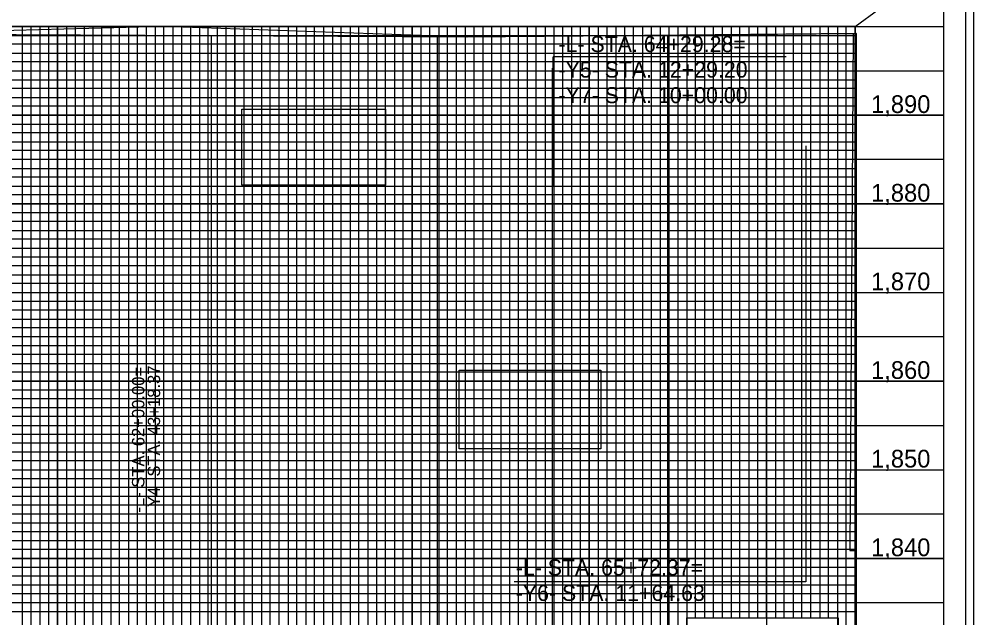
# Model space of a CAD drawing. Extents: x 557032 to 562069, y 513430 to 515874.
# Drawn here: x 558178 to 558716, y 514991 to 515328 of the extents above; entities that cross this region are included whole.
import ezdxf

# ---------------------------------------------------------------- set-up
doc = ezdxf.new("R2010")
doc.units = 0
for name, color, linetype in [('Exist Vertical Profile Vertical Axis Label', 7, 'Continuous'), ('Prop DSN Text', 7, 'Continuous'), ('Prop Vertical Profile Curve Label', 7, 'Continuous'), ('Prop VPI Label', 7, 'Continuous'), ('Scratch_Level_1', 7, 'Continuous'), ('Scratch_Level_5', 7, 'Continuous'), ('Sheet DOT Grid CELL', 7, 'Continuous'), ('Sheet Layout Profile Border Port 2', 7, 'Continuous'), ('Sheet Plot Border Inside CELL', 7, 'Continuous'), ('Sheet Plot Border Outside CELL', 7, 'Continuous'), ('Sheet Profile CELL', 7, 'Continuous'), ('Sheet Profile Grid Major CELL', 7, 'Continuous'), ('Sheet Profile Grid Middle CELL', 7, 'Continuous'), ('Sheet Profile Grid Minor CELL', 7, 'Continuous')]:
    doc.layers.add(name, color=color, linetype=linetype)

msp = doc.modelspace()

# ---------------------------------------------------------------- linework, layer by layer
at = {"layer": 'Prop DSN Text'}
for p, q in [((558554.45, 514990.68), (558639.79, 514990.68)), ((558554.45, 514914.28), (558554.45, 514990.68)), ((558639.79, 514990.68), (558639.79, 514914.28))]:
    msp.add_line(p, q, dxfattribs=at)
at = {"layer": 'Prop Vertical Profile Curve Label'}
for points in [[(558303.41, 515277.61), (558384.45, 515277.61), (558384.45, 515234.81), (558303.41, 515234.81)], [(558426.01, 515130.35), (558506.01, 515130.35), (558506.01, 515086.06), (558426.01, 515086.06)]]:
    msp.add_lwpolyline(points, close=True, dxfattribs=at)
at = {"layer": 'Prop VPI Label'}
for p, q in [((558478.96, 515234.55), (558478.96, 515307.14)), ((558610.53, 515307.14), (558478.96, 515307.14)), ((558621.61, 515257.07), (558621.61, 515011.1)), ((558249.45, 515175.19), (558249.45, 515046.94)), ((558621.61, 515011.1), (558457.09, 515011.1))]:
    msp.add_line(p, q, dxfattribs=at)
at = {"layer": 'Scratch_Level_1'}
msp.add_line((558286.33, 514832.76), (558286.33, 515319), dxfattribs=at)
at = {"layer": 'Scratch_Level_5'}
for p, q in [((558649.45, 515320.22), (558648.39, 515320.21)), ((558649.45, 515028.67), (558649.45, 515320.22)), ((558650.22, 514874.46), (558650.22, 515320.39)), ((558413.73, 514833.08), (558413.73, 515318.28)), ((558543.74, 514833.56), (558543.74, 515319.24)), ((558478.73, 514833.32), (558478.73, 515300.8))]:
    msp.add_line(p, q, dxfattribs=at)
for points in [[(558499.4, 515824.23), (557249.45, 515849.28), (557249.45, 515349.28), (557236.61, 515332.67), (557249.45, 515324.28), (558649.45, 515324.28), (558662.72, 515334.01), (558649.45, 515349.28), (558649.45, 515688.23), (558499.4, 515688.23)], [(557249.45, 515324.28), (557249.45, 514824.28), (557239, 514812.71), (557236.95, 514799.28), (558647.93, 514799.13), (558699.45, 514799.28), (558649.45, 514824.28), (558649.45, 515324.28)]]:
    msp.add_lwpolyline(points, close=True, dxfattribs=at)
for points in [[(558650.22, 515320.39), (558430.88, 515318.37), (558259.45, 515324.28), (558104.05, 515320.21), (557248.74, 515316.3)], [(558648.39, 515320.21), (558646.37, 515028.67), (558649.45, 515028.67)]]:
    msp.add_lwpolyline(points, dxfattribs=at)
at = {"layer": 'Sheet DOT Grid CELL'}
for p, q in [((557199.45, 515324.28), (558699.34, 515324.28)), ((558199.45, 515324.28), (558199.45, 514824.28)), ((558249.45, 515324.28), (558249.45, 514824.28)), ((558299.45, 515324.28), (558299.45, 514824.28)), ((558349.45, 515324.28), (558349.45, 514824.28)), ((558399.45, 515324.28), (558399.45, 514824.28)), ((558449.45, 515324.28), (558449.45, 514824.28)), ((558499.45, 515324.28), (558499.45, 514824.28)), ((558549.45, 515324.28), (558549.45, 514824.28)), ((558599.45, 515324.28), (558599.45, 514824.28)), ((558649.45, 515324.28), (558649.45, 514824.28)), ((557199.45, 515274.28), (558699.34, 515274.28)), ((557199.45, 515224.28), (558699.34, 515224.28)), ((557199.45, 515174.28), (558699.34, 515174.28)), ((557199.45, 515124.28), (558699.34, 515124.28)), ((557199.45, 515074.28), (558699.34, 515074.28)), ((557199.45, 515024.28), (558699.34, 515024.28))]:
    msp.add_line(p, q, dxfattribs=at)
at = {"layer": 'Sheet Layout Profile Border Port 2'}
msp.add_line((558649.45, 514833.95), (558649.45, 515320.22), dxfattribs=at)
msp.add_lwpolyline([(557249.45, 515324.28), (558649.45, 515324.28), (558649.45, 514824.28), (557249.45, 514824.28)], close=True, dxfattribs=at)
msp.add_lwpolyline([(558649.45, 515320.22), (558430.11, 515318.19), (558103.28, 515320.04), (557249.45, 515316.52)], dxfattribs=at)
at = {"layer": 'Sheet Plot Border Inside CELL'}
msp.add_lwpolyline([(557045.45, 514796.73), (558711.95, 514796.73), (558711.95, 515851.83), (557045.45, 515851.83)], close=True, dxfattribs=at)
at = {"layer": 'Sheet Plot Border Outside CELL'}
msp.add_lwpolyline([(557032.45, 514774.28), (558716.45, 514774.28), (558716.45, 515874.28), (557032.45, 515874.28)], close=True, dxfattribs=at)
at = {"layer": 'Sheet Profile CELL'}
msp.add_line((557199.45, 515324.28), (558699.45, 515324.28), dxfattribs=at)
msp.add_lwpolyline([(558699.45, 515849.28), (557199.45, 515849.28), (557199.45, 514799.28), (558699.45, 514799.28)], close=True, dxfattribs=at)
at = {"layer": 'Sheet Profile Grid Major CELL'}
for p, q in [((558199.45, 515324.28), (558249.45, 515324.28)), ((558299.45, 515324.28), (558349.45, 515324.28)), ((558399.45, 515324.28), (558449.45, 515324.28)), ((558499.45, 515324.28), (558549.45, 515324.28)), ((558599.45, 515324.28), (558649.45, 515324.28))]:
    msp.add_line(p, q, dxfattribs=at)
for points in [[(558149.45, 514824.28), (558199.45, 514824.28), (558199.45, 515324.28), (558249.45, 515324.28), (558249.45, 514824.28), (558299.45, 514824.28), (558299.45, 515324.28), (558349.45, 515324.28), (558349.45, 514824.28), (558399.45, 514824.28), (558399.45, 515324.28), (558449.45, 515324.28), (558449.45, 514824.28), (558499.45, 514824.28), (558499.45, 515324.28), (558549.45, 515324.28), (558549.45, 514824.28), (558599.45, 514824.28), (558599.45, 514824.28), (558599.45, 514964.88)], [(558599.45, 514990.68), (558599.45, 515324.28), (558649.45, 515324.28), (558649.45, 514824.28)], [(558699.45, 515274.28), (557199.45, 515274.28)], [(558699.45, 515224.28), (557199.45, 515224.28), (557199.45, 515174.28), (558699.45, 515174.28)], [(558699.45, 515124.28), (557199.45, 515124.28), (557199.45, 515074.28), (558699.45, 515074.28)], [(558699.45, 515024.28), (557199.45, 515024.28), (557199.45, 514974.28), (558554.45, 514974.28)]]:
    msp.add_lwpolyline(points, dxfattribs=at)
at = {"layer": 'Sheet Profile Grid Middle CELL'}
for points in [[(558174.45, 514824.28), (558224.45, 514824.28), (558224.45, 515324.28), (558274.45, 515324.28), (558274.45, 514824.28), (558324.45, 514824.28), (558324.45, 515324.28), (558374.45, 515324.28), (558374.45, 514824.28), (558424.45, 514824.28), (558424.45, 515324.28), (558474.45, 515324.28), (558474.45, 514824.28), (558524.45, 514824.28), (558524.45, 515324.28), (558574.45, 515324.28), (558574.45, 514990.68)], [(558624.45, 514990.68), (558624.45, 515324.28)], [(557199.45, 515299.28), (558699.45, 515299.28)], [(558699.45, 515249.28), (557199.45, 515249.28), (557199.45, 515199.28), (558699.45, 515199.28)], [(558699.45, 515149.28), (557199.45, 515149.28), (557199.45, 515099.28), (558699.45, 515099.28)], [(558699.45, 515049.28), (557199.45, 515049.28), (557199.45, 514999.28), (558699.45, 514999.28)]]:
    msp.add_lwpolyline(points, dxfattribs=at)
at = {"layer": 'Sheet Profile Grid Minor CELL'}
for p, q in [((557249.45, 515319.28), (558649.45, 515319.28)), ((558649.45, 515314.28), (557249.45, 515314.28)), ((557249.45, 515309.28), (558649.45, 515309.28)), ((558649.45, 515304.28), (557249.45, 515304.28)), ((557249.45, 515294.28), (558649.45, 515294.28)), ((558649.45, 515289.28), (557249.45, 515289.28)), ((557249.45, 515284.28), (558649.45, 515284.28)), ((558649.45, 515279.28), (557249.45, 515279.28)), ((557249.45, 515269.28), (558649.45, 515269.28)), ((558649.45, 515264.28), (557249.45, 515264.28)), ((557249.45, 515259.28), (558649.45, 515259.28)), ((558649.45, 515254.28), (557249.45, 515254.28)), ((557249.45, 515244.28), (558649.45, 515244.28)), ((558649.45, 515239.28), (557249.45, 515239.28)), ((557249.45, 515234.28), (558649.45, 515234.28)), ((558649.45, 515229.28), (557249.45, 515229.28)), ((557249.45, 515219.28), (558649.45, 515219.28)), ((558649.45, 515214.28), (557249.45, 515214.28)), ((557249.45, 515209.28), (558649.45, 515209.28)), ((558649.45, 515204.28), (557249.45, 515204.28)), ((557249.45, 515194.28), (558649.45, 515194.28)), ((558649.45, 515189.28), (557249.45, 515189.28)), ((557249.45, 515184.28), (558649.45, 515184.28)), ((558649.45, 515179.28), (557249.45, 515179.28)), ((557249.45, 515169.28), (558649.45, 515169.28)), ((558649.45, 515164.28), (557249.45, 515164.28)), ((557249.45, 515159.28), (558649.45, 515159.28)), ((558649.45, 515154.28), (557249.45, 515154.28)), ((557249.45, 515144.28), (558649.45, 515144.28)), ((558649.45, 515139.28), (557249.45, 515139.28)), ((557249.45, 515134.28), (558649.45, 515134.28)), ((558649.45, 515129.28), (557249.45, 515129.43)), ((557249.45, 515119.28), (558649.45, 515119.28)), ((558649.45, 515114.28), (557249.45, 515114.28)), ((557249.45, 515109.28), (558649.45, 515109.28)), ((558649.45, 515104.28), (557249.45, 515104.28)), ((557249.45, 515094.28), (558649.45, 515094.28)), ((558649.45, 515089.28), (557249.45, 515089.28)), ((557249.45, 515084.28), (558649.45, 515084.28)), ((558649.45, 515079.28), (557249.45, 515079.28)), ((557249.45, 515069.28), (558649.45, 515069.28)), ((558649.45, 515064.28), (557249.45, 515064.28)), ((557249.45, 515059.28), (558649.45, 515059.28)), ((558649.45, 515054.28), (557249.45, 515054.28)), ((557249.45, 515044.28), (558649.45, 515044.28)), ((558649.45, 515039.28), (557249.45, 515039.28)), ((557249.45, 515034.28), (558649.45, 515034.28)), ((558649.45, 515029.28), (557249.45, 515029.28)), ((557249.45, 515019.28), (558649.45, 515019.28)), ((558649.45, 515014.28), (557249.45, 515014.28)), ((557249.45, 515009.28), (558649.45, 515009.28)), ((558649.45, 515004.28), (557249.45, 515004.28)), ((557249.45, 514994.28), (558649.45, 514994.28))]:
    msp.add_line(p, q, dxfattribs=at)
for points in [[(558169.45, 515324.28), (558179.45, 515324.28), (558179.45, 514824.28)], [(558184.45, 514824.28), (558184.45, 515324.28), (558189.45, 515324.28), (558189.45, 514824.28)], [(558194.45, 514824.28), (558194.45, 515324.28), (558204.45, 515324.28), (558204.45, 514824.28)], [(558209.45, 514824.28), (558209.45, 515324.28), (558214.45, 515324.28), (558214.45, 514824.28)], [(558219.45, 514824.28), (558219.45, 515324.28), (558229.45, 515324.28), (558229.45, 514824.28)], [(558234.45, 514824.28), (558234.45, 515324.28), (558239.45, 515324.28), (558239.45, 514824.28)], [(558244.45, 514824.28), (558244.45, 515324.28), (558254.45, 515324.28), (558254.45, 514824.28)], [(558259.45, 514824.28), (558259.45, 515324.28), (558264.45, 515324.28), (558264.45, 514824.28)], [(558269.45, 514824.28), (558269.45, 515324.28), (558279.45, 515324.28), (558279.45, 514824.28)], [(558284.45, 514824.28), (558284.45, 515324.28), (558289.45, 515324.28), (558289.45, 514824.28)], [(558294.45, 514824.28), (558294.45, 515324.28), (558304.45, 515324.28), (558304.45, 514824.28)], [(558309.45, 514824.28), (558309.45, 515324.28), (558314.45, 515324.28), (558314.45, 514824.28)], [(558319.45, 514824.28), (558319.45, 515324.28), (558329.45, 515324.28), (558329.45, 514824.28)], [(558334.45, 514824.28), (558334.45, 515324.28), (558339.45, 515324.28), (558339.45, 514824.28)], [(558344.45, 514824.28), (558344.45, 515324.28), (558354.45, 515324.28), (558354.45, 514824.28)], [(558359.45, 514824.28), (558359.45, 515324.28), (558364.45, 515324.28), (558364.45, 514824.28)], [(558369.45, 514824.28), (558369.45, 515324.28), (558379.45, 515324.28), (558379.45, 514824.28)], [(558384.45, 514824.28), (558384.45, 515324.28), (558389.45, 515324.28), (558389.45, 514824.28)], [(558394.45, 514824.28), (558394.45, 515324.28), (558404.45, 515324.28), (558404.45, 514824.28)], [(558409.45, 514824.28), (558409.45, 515324.28), (558414.45, 515324.28), (558414.45, 514824.28)], [(558419.45, 514824.28), (558419.45, 515324.28), (558429.45, 515324.28), (558429.45, 514824.28)], [(558434.45, 514824.28), (558434.45, 515324.28), (558439.45, 515324.28), (558439.45, 514824.28)], [(558444.45, 514824.28), (558444.45, 515324.28), (558454.45, 515324.28), (558454.45, 514824.28)], [(558459.45, 514824.28), (558459.45, 515324.28), (558464.45, 515324.28), (558464.45, 514824.28)], [(558469.45, 514824.28), (558469.45, 515324.28), (558479.45, 515324.28), (558479.45, 514824.28)], [(558484.45, 514824.28), (558484.45, 515324.28), (558489.45, 515324.28), (558489.45, 514824.28)], [(558494.45, 514824.28), (558494.45, 515324.28), (558504.45, 515324.28), (558504.45, 514824.28)], [(558509.45, 514824.28), (558509.45, 515324.28), (558514.45, 515324.28), (558514.45, 514824.28)], [(558519.45, 514824.28), (558519.45, 515324.28), (558529.45, 515324.28), (558529.45, 514824.28)], [(558534.45, 514824.28), (558534.45, 515324.28), (558539.45, 515324.28), (558539.45, 514824.28)], [(558544.45, 514824.28), (558544.45, 515324.28), (558554.45, 515324.28), (558554.45, 514824.28)], [(558559.45, 514990.68), (558559.45, 515324.28), (558564.45, 515324.28), (558564.45, 514990.68)], [(558569.45, 514990.68), (558569.45, 515324.28), (558579.45, 515324.28), (558579.45, 514990.68)], [(558584.45, 514990.68), (558584.45, 515324.28), (558589.45, 515324.28), (558589.45, 514990.68)], [(558594.45, 514990.68), (558594.45, 515324.28), (558604.45, 515324.28), (558604.45, 514990.68)], [(558609.45, 514990.68), (558609.45, 515324.28), (558614.45, 515324.28), (558614.45, 514990.68)], [(558619.45, 514990.68), (558619.45, 515324.28), (558629.45, 515324.28), (558629.45, 514990.68)], [(558634.45, 514990.68), (558634.45, 515324.28), (558639.45, 515324.28), (558639.45, 514824.28), (558644.45, 514824.28), (558644.45, 515324.28), (558649.45, 515324.28)]]:
    msp.add_lwpolyline(points, dxfattribs=at)

# ---------------------------------------------------------------- texts
at = {"layer": 'Exist Vertical Profile Vertical Axis Label'}
for s, p in [('1,890', (558658.44, 515275.5)), ('1,890', (558658.44, 515275.5)), ('1,880', (558658.44, 515225.5)), ('1,880', (558658.44, 515225.5)), ('1,870', (558658.44, 515175.5)), ('1,870', (558658.44, 515175.5)), ('1,860', (558658.44, 515125.5)), ('1,860', (558658.44, 515125.5)), ('1,850', (558658.44, 515075.5)), ('1,850', (558658.44, 515075.5)), ('1,840', (558658.44, 515025.5)), ('1,840', (558658.44, 515025.5))]:
    msp.add_text(s, height=10, dxfattribs=at).set_placement(p)
at = {"layer": 'Prop VPI Label'}
for s, p in [('-L- STA. 64+29.28=', (558482.05, 515309.87)), ('-Y5- STA. 12+29.20', (558482.05, 515295.47)), ('-Y7- STA. 10+00.00', (558482.05, 515281.07)), ('-L- STA. 65+72.37=', (558457.93, 515014.64)), ('-Y6- STA. 11+64.63', (558457.93, 515000.24))]:
    msp.add_text(s, height=9, dxfattribs=at).set_placement(p)
for s, p in [('-L- STA. 62+00.00=', (558248.39, 515050.07)), ('-Y4- STA. 43+18.37', (558257.26, 515050.07))]:
    msp.add_text(s, height=7, rotation=90, dxfattribs=at).set_placement(p)

doc.saveas('drawing.dxf')
